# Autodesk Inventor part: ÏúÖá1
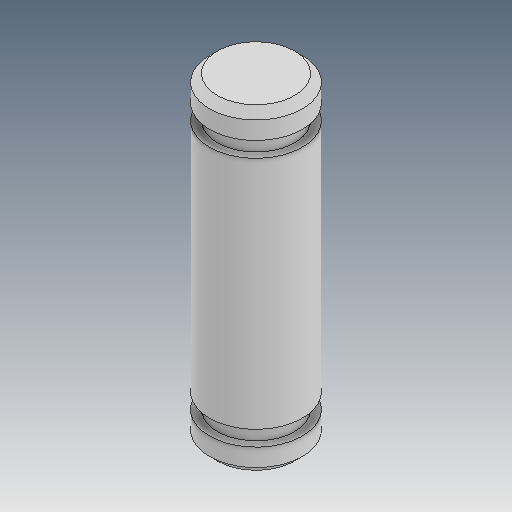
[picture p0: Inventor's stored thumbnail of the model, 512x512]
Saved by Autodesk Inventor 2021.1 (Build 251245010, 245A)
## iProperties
Created: 2019-04
Part Number: ÏúÖá1
Material: Ogólny
Document SubType Name: Modeling
Designer: user
Density: 1 g/cm^3
Appearance: Domyślna
Author: user
Revision Number: ÈÎºÎ
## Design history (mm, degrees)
feature "ÊäÈë1"
node "Bryła1"
